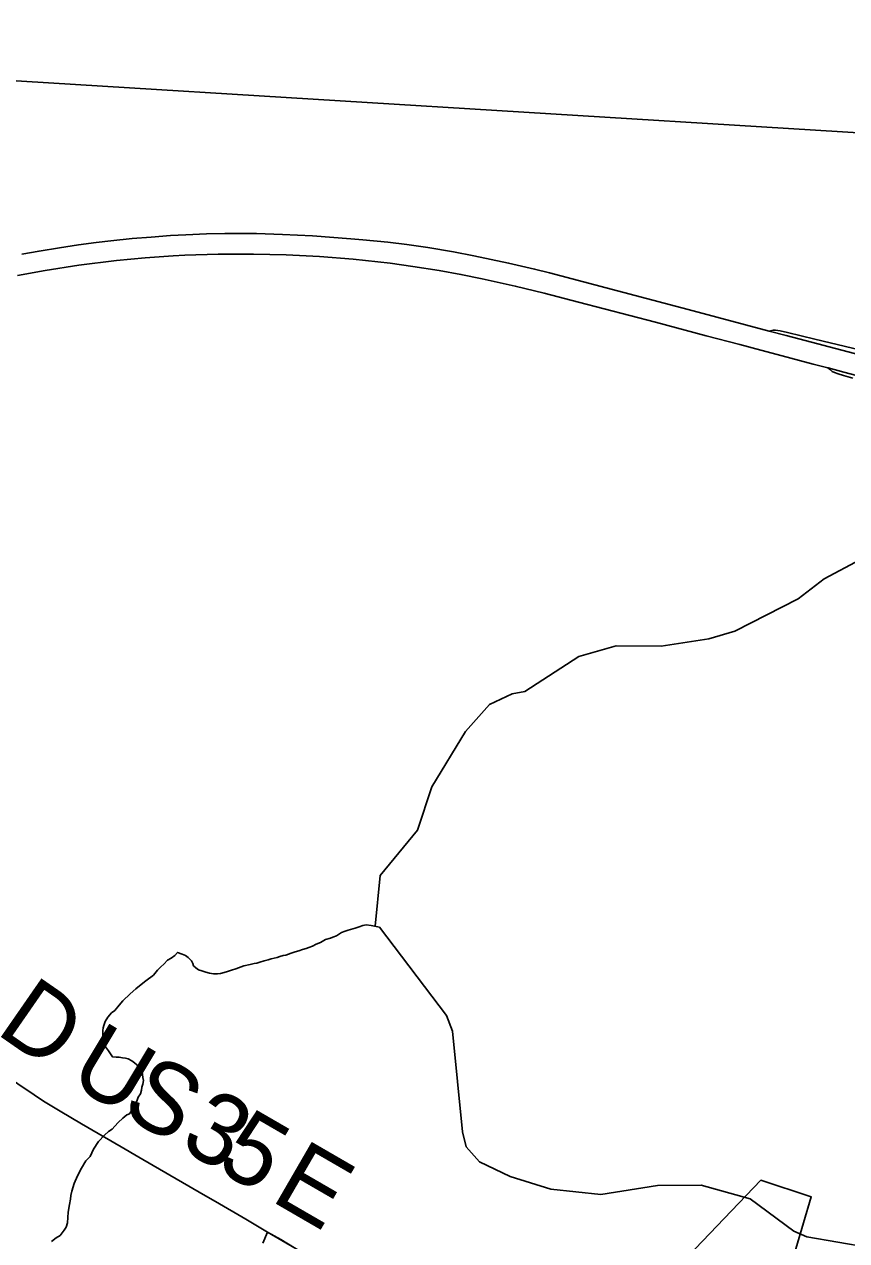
# Model space of a CAD drawing. Extents: x -13.9 to 69.1, y -25.2 to 26.1.
# Drawn here: x 3.245 to 3.861, y 17.993 to 18.903 of the extents above; entities that cross this region are included whole.
import ezdxf

# ---------------------------------------------------------------- set-up
doc = ezdxf.new("R2010")
doc.units = 0
for name, color, linetype in [('GM_X_Corporation', 7, 'Continuous'), ('GM_X_County_Road', 7, 'Continuous'), ('GM_X_County_Road_Text', 7, 'Continuous'), ('GM_X_Interchange_Ramps', 7, 'Continuous'), ('GM_X_Major_River', 7, 'Continuous'), ('GM_X_Minor_River', 7, 'Continuous'), ('GM_X_Township', 7, 'Continuous'), ('GM_X_US_Route', 7, 'Continuous')]:
    doc.layers.add(name, color=color, linetype=linetype)

msp = doc.modelspace()

# ---------------------------------------------------------------- linework, layer by layer
at = {"layer": 'GM_X_Corporation'}
for points in [[(3.7309, 17.96983), (3.79643, 18.03839), (3.83424, 18.02587), (3.78251, 17.85069)], [(3.42356, 17.99117), (3.42708, 17.99959), (3.52374, 17.94329)]]:
    msp.add_lwpolyline(points, dxfattribs=at)
at = {"layer": 'GM_X_County_Road'}
for points in [[(3.0099, 18.27569), (3.0139, 18.27279), (3.04103, 18.25335), (3.05209, 18.24546), (3.07865, 18.2262), (3.09347, 18.2158), (3.10493, 18.20752), (3.12185, 18.19539), (3.15345, 18.17255), (3.20425, 18.13627), (3.22384, 18.12229), (3.22924, 18.11821), (3.23522, 18.11397), (3.24031, 18.11043), (3.25239, 18.10216), (3.25949, 18.0976), (3.27198, 18.09003), (3.28797, 18.0806), (3.31761, 18.06335), (3.33084, 18.05565)], [(3.33084, 18.05565), (3.34142, 18.04949), (3.38083, 18.02669), (3.38812, 18.02246), (3.41091, 18.00918), (3.42708, 17.9996)], [(3.42708, 17.9996), (3.43707, 17.99387), (3.44868, 17.98701), (3.47435, 17.97188), (3.50628, 17.95306), (3.52366, 17.94279)]]:
    msp.add_lwpolyline(points, dxfattribs=at)
at = {"layer": 'GM_X_Interchange_Ramps'}
for points in [[(4.1405, 18.63631), (4.12586, 18.63492), (4.10233, 18.63138), (4.07622, 18.62694), (4.06907, 18.62593), (4.0611, 18.62505), (4.05371, 18.62467), (4.04317, 18.62429), (4.03051, 18.62492), (4.01925, 18.62605), (4.00929, 18.62732), (4.00179, 18.62883), (3.99194, 18.63084), (3.92503, 18.64697), (3.89424, 18.65429), (3.865, 18.66111), (3.83694, 18.66781), (3.81641, 18.67283), (3.81098, 18.67401), (3.8075, 18.67447), (3.80566, 18.67447), (3.80281, 18.67384)], [(3.84652, 18.64637), (3.84849, 18.64476), (3.84995, 18.64363), (3.8517, 18.64278), (3.85445, 18.64181), (3.85827, 18.64065), (3.86534, 18.63859)]]:
    msp.add_lwpolyline(points, dxfattribs=at)
at = {"layer": 'GM_X_Major_River'}
for points in [[(3.33383, 18.11018), (3.3342, 18.11309), (3.33388, 18.11527), (3.33356, 18.11746), (3.33324, 18.11928), (3.33092, 18.12294), (3.32925, 18.12478), (3.32757, 18.12625), (3.32556, 18.12773), (3.32287, 18.12921), (3.32085, 18.1296), (3.31849, 18.12999), (3.31614, 18.13038), (3.31377, 18.1304), (3.31108, 18.1308), (3.30808, 18.13519), (3.30574, 18.13813), (3.30407, 18.13996), (3.30378, 18.14469), (3.30381, 18.14797), (3.30384, 18.15051), (3.30419, 18.15232), (3.30455, 18.15414), (3.30559, 18.15704), (3.30765, 18.16029), (3.31038, 18.16353), (3.31276, 18.16532), (3.31618, 18.16928), (3.31891, 18.17252), (3.32436, 18.17791), (3.32845, 18.1815), (3.33253, 18.18473), (3.33594, 18.1876), (3.34172, 18.1919), (3.34479, 18.1955), (3.34718, 18.19802), (3.34956, 18.20017), (3.35229, 18.20305), (3.35501, 18.20448), (3.35773, 18.20663), (3.35978, 18.20879), (3.36314, 18.20766), (3.36583, 18.20654), (3.36784, 18.20506), (3.37018, 18.20249), (3.37118, 18.20066), (3.37183, 18.19883), (3.37351, 18.19736), (3.37552, 18.19589), (3.37787, 18.19513), (3.3809, 18.19401), (3.38359, 18.19325), (3.38663, 18.19285), (3.38967, 18.19282), (3.39203, 18.19316), (3.39474, 18.19385), (3.39711, 18.19455), (3.40016, 18.19561), (3.40355, 18.19666), (3.40931, 18.19878), (3.41405, 18.19982), (3.41709, 18.20051), (3.41912, 18.20085), (3.42149, 18.20155), (3.42454, 18.20261), (3.42758, 18.2033), (3.42995, 18.204), (3.43435, 18.20505), (3.43639, 18.20575), (3.43875, 18.20645), (3.44079, 18.20679), (3.44282, 18.2075), (3.44485, 18.2082), (3.4479, 18.20926), (3.45061, 18.20995), (3.45332, 18.21102), (3.45602, 18.21171), (3.45806, 18.21242), (3.46077, 18.21348), (3.46348, 18.2149), (3.46687, 18.21632), (3.47061, 18.21846), (3.47433, 18.21951), (3.47603, 18.22021), (3.47874, 18.22128), (3.48248, 18.22378), (3.48519, 18.22484), (3.48756, 18.22554), (3.48925, 18.22589), (3.49094, 18.22659), (3.49264, 18.22694), (3.49569, 18.228), (3.4984, 18.22906), (3.5011, 18.22939), (3.50481, 18.22898), (3.51097, 18.22783)], [(3.51097, 18.22783), (3.56125, 18.16166), (3.56574, 18.14994), (3.57309, 18.07456), (3.57591, 18.06324), (3.5858, 18.05212), (3.60882, 18.04108), (3.63927, 18.0317), (3.67655, 18.02761), (3.71908, 18.03432), (3.75174, 18.03469), (3.78857, 18.02444), (3.8211, 18.00011), (3.83078, 17.9959), (3.87742, 17.98798)], [(3.2655, 17.99243), (3.2689, 17.9953), (3.27196, 17.99708), (3.27504, 18.00105), (3.27641, 18.00321), (3.27745, 18.00647), (3.27787, 18.01447), (3.27894, 18.02027), (3.27965, 18.02426), (3.28001, 18.0268), (3.28072, 18.03007), (3.28246, 18.03586), (3.28488, 18.04165), (3.28798, 18.04743), (3.29107, 18.05285), (3.29448, 18.05609), (3.29689, 18.06152), (3.30066, 18.06729), (3.3051, 18.07197), (3.30816, 18.07484), (3.31088, 18.07663), (3.31293, 18.07879), (3.31532, 18.08167), (3.31873, 18.0849), (3.32179, 18.08741), (3.32383, 18.08812), (3.3252, 18.09028), (3.32726, 18.09426), (3.32932, 18.09751), (3.33036, 18.10041), (3.33207, 18.10293), (3.33278, 18.10583), (3.33313, 18.10801), (3.33383, 18.11018)]]:
    msp.add_lwpolyline(points, dxfattribs=at)
at = {"layer": 'GM_X_Minor_River'}
for points in [[(3.51151, 18.26647), (3.53945, 18.30027), (3.5501, 18.33277), (3.5754, 18.37409), (3.59326, 18.39446), (3.61025, 18.40249), (3.61972, 18.40412), (3.66027, 18.43023), (3.68805, 18.43841), (3.72176, 18.43811), (3.75758, 18.44359), (3.77689, 18.44939), (3.82449, 18.47354), (3.84395, 18.48843), (3.87116, 18.5028), (3.89307, 18.50237), (3.90312, 18.49854), (3.9132, 18.49653), (3.92196, 18.49599), (3.93045, 18.49982), (3.95215, 18.52776), (3.9672, 18.56128)], [(3.51151, 18.26648), (3.50773, 18.22844)]]:
    msp.add_lwpolyline(points, dxfattribs=at)
at = {"layer": 'GM_X_Township'}
msp.add_lwpolyline([(8.09762, 21.21449), (2.66796, 21.21449), (2.57127, 21.12489), (2.5376, 21.09327), (2.52067, 21.07738), (2.92824, 20.52825), (2.31491, 19.99428), (2.33455, 19.99242), (2.41858, 19.98901), (2.46919, 19.98696), (2.51761, 19.98703), (2.59954, 20.01177), (2.57136, 18.90232), (4.52881, 18.78157), (7.86611, 18.45895), (7.9988, 20.03824), (8.04284, 20.56246)], close=True, dxfattribs=at)
msp.add_lwpolyline([(7.86611, 18.45895), (4.52881, 18.78157), (2.57136, 18.90232), (2.23038, 17.24665), (2.17937, 16.53249), (2.17111, 16.462), (2.21595, 16.45704), (2.20226, 16.14501)], dxfattribs=at)
at = {"layer": 'GM_X_US_Route'}
for points in [[(3.2431, 18.73143), (3.25619, 18.73372), (3.27149, 18.73615), (3.28569, 18.73839), (3.29884, 18.74018), (3.30982, 18.74141), (3.32576, 18.74307), (3.34008, 18.74425), (3.3544, 18.74536), (3.36599, 18.74594), (3.38144, 18.74659), (3.39524, 18.74685), (3.41015, 18.74687), (3.41899, 18.74678), (3.43831, 18.74625), (3.46093, 18.74503), (3.48959, 18.74291), (3.4984, 18.74216), (3.5171, 18.74028), (3.53137, 18.73859), (3.54725, 18.73637), (3.56634, 18.73314), (3.58157, 18.73026), (3.60759, 18.72477), (3.62703, 18.72027), (3.63834, 18.71747), (3.68075, 18.70632), (3.74568, 18.68903), (3.80281, 18.67384), (3.81544, 18.67048), (3.8713, 18.65584)], [(3.24006, 18.71549), (3.26079, 18.71923), (3.28598, 18.72312), (3.31401, 18.72658), (3.33549, 18.72879), (3.35648, 18.73026), (3.36532, 18.73071), (3.39021, 18.73143), (3.41676, 18.73145), (3.4411, 18.73085), (3.46597, 18.72964), (3.49135, 18.72757), (3.51886, 18.72456), (3.53589, 18.72229), (3.5556, 18.71923), (3.57197, 18.71625), (3.58773, 18.71305), (3.61266, 18.70754), (3.63425, 18.70232), (3.66003, 18.69553), (3.71749, 18.68046), (3.7556, 18.67038), (3.78084, 18.66372), (3.7964, 18.65961), (3.80874, 18.65628), (3.83557, 18.6492), (3.84652, 18.64637), (3.84686, 18.64628), (3.85867, 18.64315), (3.9059, 18.63063)]]:
    msp.add_lwpolyline(points, dxfattribs=at)

# ---------------------------------------------------------------- texts
at = {"layer": 'GM_X_County_Road_Text'}
for s, height, rotation, p in [('D', 0.05328, 325.25609, (3.22271, 18.14893)), ('U', 0.05349, 329.00342, (3.27645, 18.11246)), ('S', 0.05354, 329.93037, (3.31604, 18.08868)), ('3', 0.05354, 329.92791, (3.35978, 18.06335)), ('5', 0.05354, 329.92791, (3.3872, 18.04748)), ('E', 0.05354, 329.92777, (3.42833, 18.02366))]:
    msp.add_text(s, height=height, rotation=rotation, dxfattribs=at).set_placement(p)

doc.saveas('drawing.dxf')
